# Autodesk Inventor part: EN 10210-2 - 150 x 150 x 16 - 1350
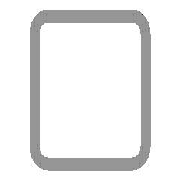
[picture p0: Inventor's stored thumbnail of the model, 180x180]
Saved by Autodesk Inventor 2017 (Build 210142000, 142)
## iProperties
Created: 2016-02
Part Number: EN 10210-2 - 150 x 150 x 16 - 1350
Material: Steel, Mild
Description: Tube
Document SubType Name: Modeling
Standard: DIN
Designer: iusti
Standard Revision: 2006-07
Standards Organization: DIN
Language: en-US
Size Designation: 150 x 150 x 16
Categories: <MemberInstance><Categories><Category DisplayName="Structural Shapes" InternalName="089c4875-fa83-4c05-b084-43b9cc11f5ed" Mnemonic="GRDR"><CategoryParameter Dis
Stock Number: 150 x 150 x 16
Mass: 87973.1 g
Surface Area: 13710.9 cm^2
Volume: 11206.8 cm^3
Density: 7.85 g/cm^3
Appearance: Semi-Polished
IsCustomPart: 1
_CCFamilyMember: 70
_CCFamilyDisplayName: DIN EN 10210-2 (Square) - Tube — Sizes in parentheses have been withdrawn
_FrameMemberDoc: Frame Member File
_Version: 15.0.0
_GetPNFromCC: 1
Author: iusti
G_L: 1350.000 mm
G_W: 150.000 mm
G_H: 150.000 mm
+1F40A12F-18AA-463D-A96A-E52DF7E897F8+CUTDETAIL1: Cut
+43047DDA-1D0B-4A2A-BC5D-95364EC01667+CUTDETAIL2: Cut
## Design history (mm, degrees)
node "Start plane"
node "End plane"
sketch "Sketch"
  geometry: L1 (-75, -51)-(-75, 51); L2 (-51, 75)-(51, 75); L3 (75, 51)-(75, -51); L4 (51, -75)-(-51, -75); L5 (-43, 59)-(43, 59); L6 (59, 43)-(59, -43); L7 (43, -59)-(-43, -59); L8 (-59, -43)-(-59, 43); L9 (0, 111.959)-(0, -111.959) reference; L10 (-111.959, 0)-(111.959, 0) reference; A1 r 24 centre (-51, -51) between (-75, -51) and (-51, -75); A2 r 24 centre (-51, 51) between (-51, 75) and (-75, 51); A3 r 24 centre (51, 51) between (75, 51) and (51, 75); A4 r 24 centre (51, -51) between (51, -75) and (75, -51); A5 r 16 centre (-43, -43) between (-59, -43) and (-43, -59); A6 r 16 centre (-43, 43) between (-43, 59) and (-59, 43); A7 r 16 centre (43, 43) between (59, 43) and (43, 59); A8 r 16 centre (43, -43) between (43, -59) and (59, -43)
  constraints: 16 end point, 16 point on circle, 16 tangent, 8 centre point, 6 equal radius, 4 parallel, 2 perpendicular, 2 other
  dimensions: "d7" = 24 radius of A1 (= G_IR); "d10" = 150 distance between parallel lines of L2 L4 (= G_H); "d11" = 150 distance between parallel lines of L1 L3 (= G_W); "d12" = 16 distance between parallel lines of L3 L6 (= G_T); "d15" = 75 distance between parallel lines of L2 L10 (= 0.5 x d10); "d16" = 75 distance between parallel lines of L9 L3 (= 0.5 x d11); "d19" = 16 radius of A5 (= G_T); "d20" = 16 distance between parallel lines of L4 L7 (= G_T)
extrude "Body" new body sketch "Sketch" stored distance "d3" = 1350 (= G_L); taper "d4" = 0 deg
node "Driven Length"
  sketch "Sketch3"
    geometry: L1 (0, 0)-(10, 0) reference
    constraints: 2 end point, 1 horizontal
  workplane "Work Plane3"
  sketch "Sketch4"
    geometry: L1 (-2, 75)-(12, 75) reference; L2 (-2, 1425)-(12, 1425) reference
    dimensions: "d18" = 1350 distance between parallel lines of L1 L2 (derived)
workplane "Work Plane4"
split "Split1"
workplane "Work Plane5"
split "Split2"
body "Solid1"
other parameters: "G_W" = 150 [user parameter; used in 1 equation term], "G_H" = 150 [user parameter; used in 1 equation term], "G_T" = 16 [user parameter; used in 3 equation terms], "G_IR" = 24 [user parameter; used in 1 equation term], "G_L" = 1350 (= d18) [user parameter; used in 1 equation term], "G_OFFSET_START" = -75 [user parameter; used in 1 equation term], "G_OFFSET_END" = -75 [user parameter; used in 1 equation term], "d13" = 75 (= -G_OFFSET_START), "d14" = 1425 (= G_OFFSET_END + B_L), "d17" = 90 deg
